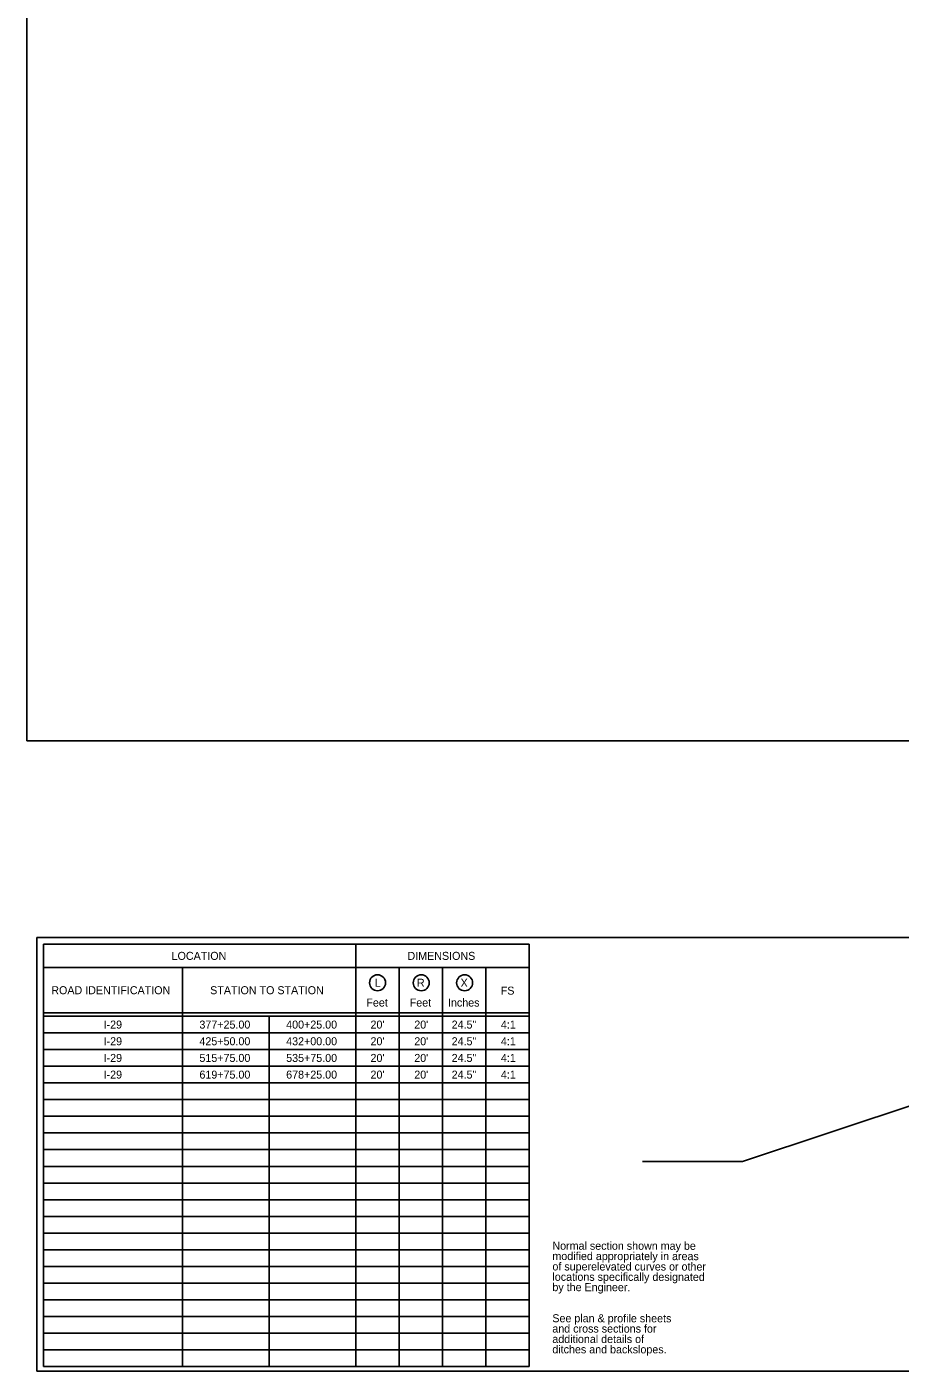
# Model space of a CAD drawing. Extents: x 10133 to 81668, y 6979 to 11018.
# Drawn here: x 10133 to 11441, y 6979 to 8994 of the extents above; entities that cross this region are included whole.
import ezdxf

# ---------------------------------------------------------------- set-up
doc = ezdxf.new("R2010")
doc.units = 0
for name, color, linetype in [('brgPreGradingNew', 7, 'Continuous'), ('brgPreStructureAlternateA', 7, 'Continuous'), ('brgPreStructureNew', 7, 'Continuous'), ('dsnCellElements', 7, 'Continuous'), ('dsnStdPattern', 7, 'Continuous'), ('Level 11', 7, 'Continuous')]:
    doc.layers.add(name, color=color, linetype=linetype)

msp = doc.modelspace()

# ---------------------------------------------------------------- linework, layer by layer
at = {"layer": 'brgPreGradingNew'}
for p, q in [((10157.5, 7619), (10885.5, 7619)), ((10157.5, 6986), (10157.5, 7619)), ((10625.5, 6986), (10625.5, 7619)), ((10885.5, 6986), (10885.5, 7619)), ((10157.5, 7584), (10885.5, 7584)), ((10365.5, 6986), (10365.5, 7584)), ((10690.5, 7584), (10690.5, 6986)), ((10755.5, 7584), (10755.5, 6986)), ((10820.5, 7584), (10820.5, 6986)), ((10157.5, 7516), (10885.5, 7516)), ((10157.5, 7511), (10885.5, 7511)), ((10495.5, 6986), (10495.5, 7511)), ((10157.5, 7486), (10885.5, 7486)), ((10157.5, 7461), (10885.5, 7461)), ((10157.5, 7436), (10885.5, 7436)), ((10157.5, 7411), (10885.5, 7411)), ((10157.5, 7386), (10885.5, 7386)), ((10157.5, 7361), (10885.5, 7361)), ((10157.5, 7336), (10885.5, 7336)), ((10157.5, 7311), (10885.5, 7311)), ((10157.5, 7286), (10885.5, 7286)), ((10157.5, 7261), (10885.5, 7261)), ((10157.5, 7236), (10885.5, 7236)), ((10157.5, 7211), (10885.5, 7211)), ((10157.5, 7186), (10885.5, 7186)), ((10157.5, 7161), (10885.5, 7161)), ((10157.5, 7136), (10885.5, 7136)), ((10157.5, 7111), (10885.5, 7111)), ((10157.5, 7086), (10885.5, 7086)), ((10157.5, 7061), (10885.5, 7061)), ((10157.5, 7036), (10885.5, 7036)), ((10157.5, 7011), (10885.5, 7011)), ((10157.5, 6986), (10885.5, 6986))]:
    msp.add_line(p, q, dxfattribs=at)
at = {"layer": 'brgPreStructureAlternateA'}
for p, q in [((11472.6, 7382.4), (11205, 7293.2)), ((11205, 7293.2), (11055, 7293.2))]:
    msp.add_line(p, q, dxfattribs=at)
at = {"layer": 'brgPreStructureNew'}
for centre in [(10658, 7561.2), (10723.6, 7561.1), (10788.6, 7561.1)]:
    msp.add_circle(centre, 12, dxfattribs=at)
at = {"layer": 'dsnCellElements'}
msp.add_lwpolyline([(10147.5, 7629), (13252.5, 7629), (13252.5, 6979), (10147.5, 6979), (10147.5, 7629)], dxfattribs=at)
at = {"layer": 'Level 11'}
msp.add_lwpolyline([(10132.5, 9944), (13267.5, 9944), (13267.5, 7924), (10132.5, 7924)], close=True, dxfattribs=at)

# ---------------------------------------------------------------- texts
at = {"layer": 'brgPreGradingNew'}
for s, p in [('LOCATION', (10349.4, 7595.5)), ('DIMENSIONS', (10702.9, 7595.5)), ('ROAD IDENTIFICATION', (10169.1, 7544)), ('STATION TO STATION', (10407.2, 7544)), ('Feet', (10641.3, 7525.5)), ('Feet', (10706.3, 7525.5)), ('Inches', (10763.6, 7525.5)), ('I-29', (10247.5, 7492.5)), ('377+25.00', (10391.1, 7492.5)), ('400+25.00', (10521.1, 7492.5)), ("20'", (10647.5, 7492.5)), ("20'", (10713.1, 7492.5)), ('24.5"', (10769.1, 7492.5)), ('4:1', (10842.9, 7492.5)), ('I-29', (10247.5, 7467.5)), ('425+50.00', (10391.1, 7467.5)), ('432+00.00', (10521.1, 7467.5)), ("20'", (10647.5, 7467.5)), ("20'", (10713.1, 7467.5)), ('24.5"', (10769.1, 7467.5)), ('4:1', (10842.9, 7467.5)), ('I-29', (10247.5, 7442.5)), ('515+75.00', (10391.1, 7442.5)), ('535+75.00', (10521.1, 7442.5)), ("20'", (10647.5, 7442.5)), ("20'", (10713.1, 7442.5)), ('24.5"', (10769.1, 7442.5)), ('4:1', (10842.9, 7442.5)), ('I-29', (10247.5, 7417.5)), ('619+75.00', (10391.1, 7417.5)), ('678+25.00', (10521.1, 7417.5)), ("20'", (10647.5, 7417.5)), ("20'", (10713.1, 7417.5)), ('24.5"', (10769.1, 7417.5)), ('4:1', (10842.9, 7417.5))]:
    msp.add_text(s, height=12, dxfattribs=at).set_placement(p)
at = {"layer": 'brgPreStructureNew'}
for s, p in [('L', (10653.7, 7555.2)), ('R', (10717.1, 7555.2)), ('X', (10782.5, 7555.2)), ('FS', (10842.7, 7543.4))]:
    msp.add_text(s, height=12, dxfattribs=at).set_placement(p)
at = {"layer": 'dsnStdPattern'}
for s, p in [('modified appropriately in areas', (10920.1, 7145.5)), ('Normal section shown may be', (10920.1, 7161)), ('of superelevated curves or other', (10920.1, 7129.9)), ('locations specifically designated', (10920.1, 7114.4)), ('by the Engineer.', (10920.1, 7098.9)), ('See plan & profile sheets', (10920, 7052.3)), ('and cross sections for', (10920, 7036.8)), ('additional details of', (10920, 7021.2)), ('ditches and backslopes.', (10920, 7005.7))]:
    msp.add_text(s, height=12, rotation=359.9583, dxfattribs=at).set_placement(p)

doc.saveas('drawing.dxf')
